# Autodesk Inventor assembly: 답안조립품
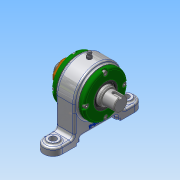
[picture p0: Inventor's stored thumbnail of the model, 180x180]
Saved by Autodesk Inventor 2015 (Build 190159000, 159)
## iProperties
Created: 2019-05
Part Number: 답안조립품
Document SubType Name: Assembly
Designer: user
Author: user
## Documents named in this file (13)
- C:\Users\user\Desktop\490504V1008\답안조립품.iam
- C:\Users\user\Desktop\490504V1008\본체.ipt
- C:\Users\user\Desktop\490504V1008\축.ipt
- C:\Users\user\Desktop\490504V1008\칼라.ipt
- C:\Users\user\Desktop\490504V1008\베어링너트.ipt
- C:\Users\user\Desktop\490504V1008\그리스니플개스킷.ipt
- C:\Users\user\Desktop\490504V1008\그리스니플 M6.ipt
- 그리스니플  M6.ipt
- C:\Users\user\Desktop\490504V1008\커버.ipt
- C:\Users\user\Desktop\490504V1008\오일 실 28 40 5 B.ipt
- C:\Users\user\Desktop\490504V1008\개스킷.ipt
- C:\Users\user\Desktop\490504V1008\앵귤러 볼 베어링 7205.ipt
- C:\Users\user\Desktop\490504V1008\볼트 M4.ipt
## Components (4 placed, 3 different names)
1. 그리스니플개스킷:1
2. 그리스니플  M6:1
3. 개스킷:1
4. 개스킷:2
